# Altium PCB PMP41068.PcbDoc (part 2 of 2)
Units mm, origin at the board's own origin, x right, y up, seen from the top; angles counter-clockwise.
Board outline 71 x 50.75 mm, 4 copper layers (Top Layer, 02IS01, 03IS02, Bottom Layer), stack 0.651 mm thick; 102 components, 48 nets, 246 pads, 360 vias.
Unrouted connection lines stored in the file: 1.
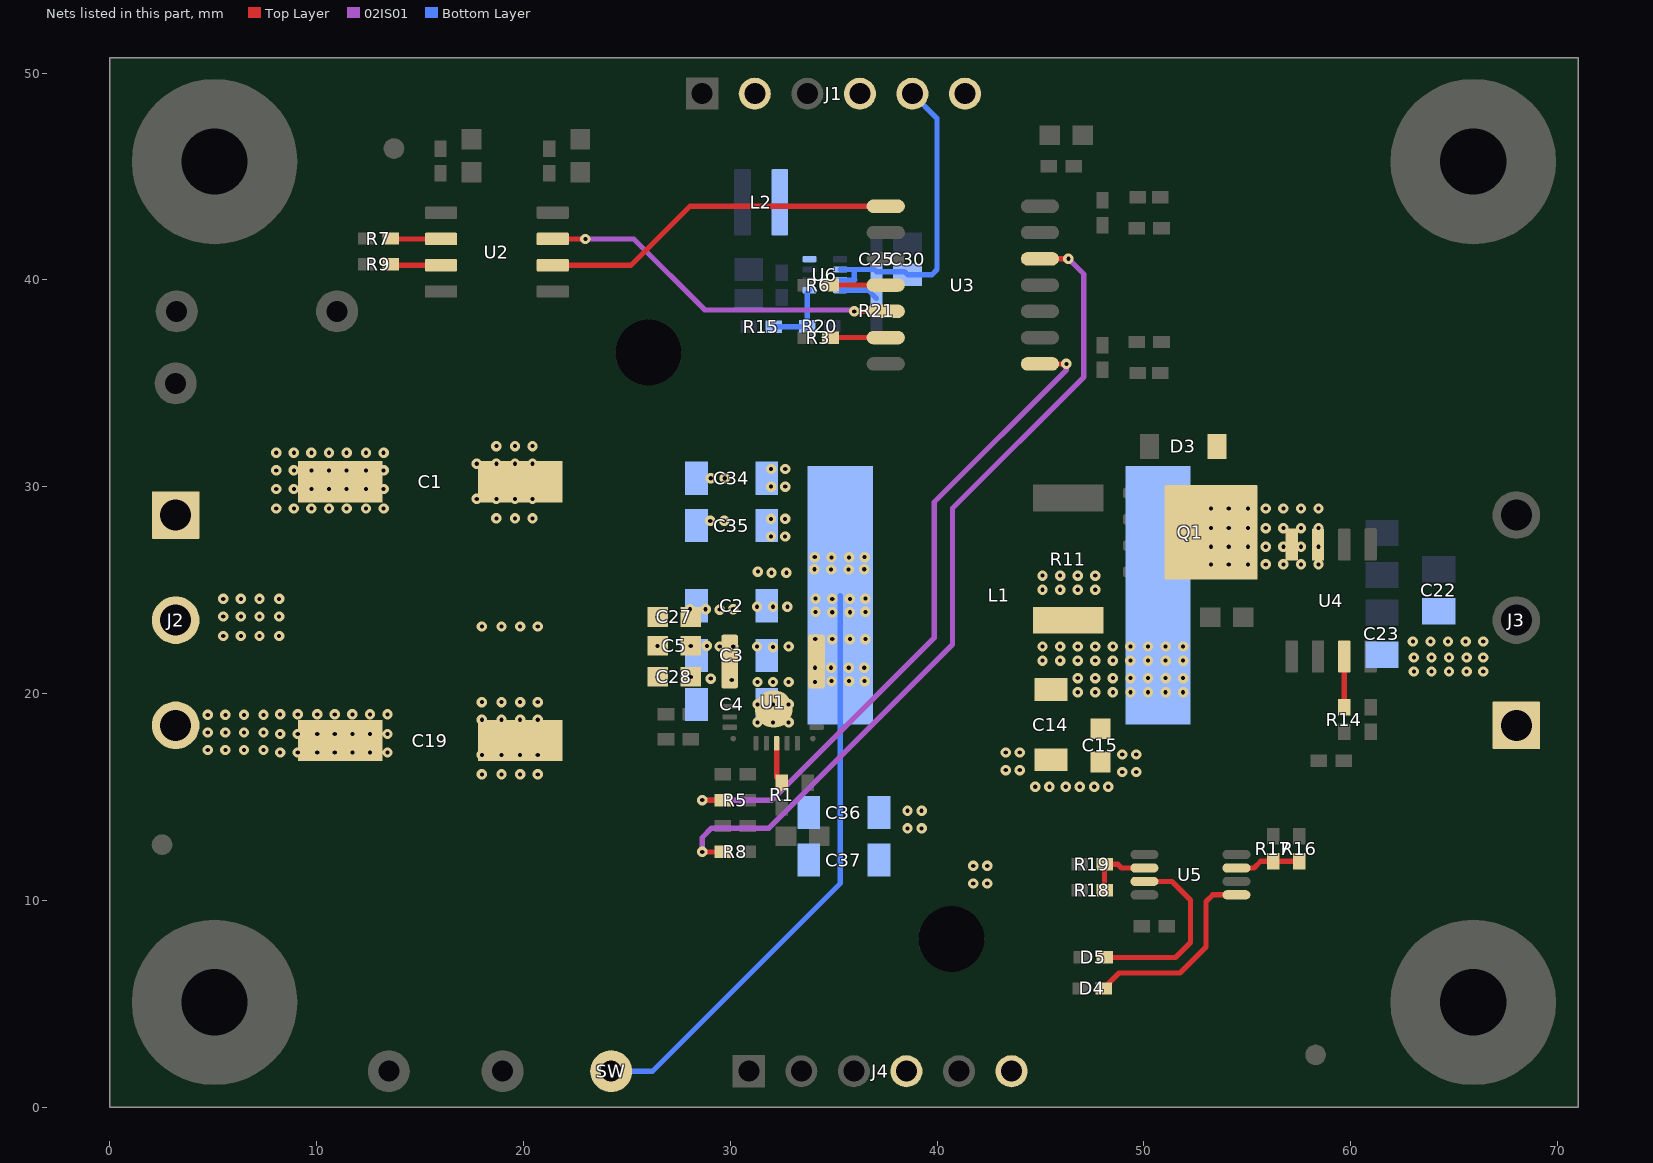
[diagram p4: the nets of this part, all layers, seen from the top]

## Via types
v1: diameter 0.5, hole 0.2, Top Layer to Bottom Layer, tented both sides, 360 vias

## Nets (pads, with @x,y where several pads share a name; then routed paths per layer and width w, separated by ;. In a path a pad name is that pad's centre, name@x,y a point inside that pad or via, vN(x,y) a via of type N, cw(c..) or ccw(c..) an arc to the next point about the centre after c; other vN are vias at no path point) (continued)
NetD3_2: D3.2 Q1.5 Q1.6 Q1.7 Q1.8 Q1.9@53.25,27.795 U4.3 U4.4
  other v1: 53.25,26.25 54.1,26.25 55.04,26.25 55.89,26.25 56.74,26.25 57.59,26.25 58.44,26.25 53.25,27.1 54.1,27.1 55.04,27.1 55.89,27.1 56.74,27.1 57.59,27.1 58.44,27.1 53.25,28 54.1,28 55.04,28 55.89,28 56.74,28 57.59,28 58.44,28 53.25,28.948 54.1,28.948 55.04,28.948 55.89,28.948 56.74,28.948 57.59,28.948 58.44,28.948
NetD4_2: D4.2 U5.1 | length 9.6
  Top Layer w0.254: D4.2@48.05,5.75 48.8,6.5 51.75,6.5 53,7.75 53,9.95 53.325,10.275 U5.1@54.475,10.275
NetD5_2: D5.2 U5.7 | length 9.1
  Top Layer w0.254: D5.2@48.1,7.25 51.525,7.25 52.25,7.975 52.25,10.025 51.35,10.925 U5.7@50.025,10.925
NetL1_1: L1.1 SW.1 U1.5 | length 28.8
  Bottom Layer w0.254: SW.1@24.25,1.75 26.25,1.75 35.325,10.825 L1.1@35.325,24.75
  other v1: 34.095,20.564 34.9,20.604 35.75,20.604 36.5,20.604 34.095,21.252 34.88,21.25 35.73,21.25 36.48,21.25 34.114,22.638 34.935,22.638 35.785,22.638 36.535,22.638 34.935,23.936 35.785,23.936 34.127,23.952 36.535,23.952 34.127,24.595 34.935,24.58 35.785,24.58 36.535,24.595 34.071,26.015 34.879,26 35.729,26 36.479,26.015 34.092,26.602 34.9,26.587 35.75,26.587 36.5,26.602
NetL2_1: L2.1 U6.4
NetR3_1: R3.1 U3.6 | length 2.7
  Top Layer w0.254: R3.1@34.85,37.21 U3.6@37.525,37.21
NetR5_1: R5.1 U3.8 | length 32.6
  Top Layer w0.254: v1(28.65,14.852) R5.1@29.65,14.852 ; U3.8@44.975,35.94 v1(46.25,35.94)
  02IS01 w0.254: v1(28.65,14.852) 32.026,14.852 39.861,22.687 39.861,29.25 46.25,35.639 v1(46.25,35.94)
NetR6_1: R6.1 U3.4 | length 2.7
  Top Layer w0.254: R6.1@34.85,39.75 U3.4@37.525,39.75
NetR7_2: R7.2 U2.2 | length 2.4
  Top Layer w0.254: R7.2@13.6,42 13.62,41.98 U2.2@16,41.98
NetR8_1: R8.1 U3.12 | length 40.6
  Top Layer w0.254: v1(28.65,12.352) R8.1@29.65,12.352 ; U3.12@44.975,41.02 v1(46.35,41.02)
  02IS01 w0.254: v1(28.65,12.352) 28.65,13.053 29.097,13.5 31.877,13.5 40.75,22.373 40.75,28.963 47.097,35.309 47.097,40.273 v1(46.35,41.02)
NetR9_2: R9.2 U2.3 | length 2.4
  Top Layer w0.254: R9.2@13.6,40.75 13.64,40.71 U2.3@16,40.71
NetR14_2: R14.2 U4.7 | length 2.4
  Top Layer w0.254: R14.2@59.685,19.35 U4.7@59.685,21.8
NetR15_1: R15.1 R20.2 U6.1 | length 3.4
  Bottom Layer w0.254: R15.1@32.1,37.73 33.705,37.73 R20.2@33.725,37.75 33.725,39.39 U6.1@33.835,39.5
NetR16_1: R16.1 R17.2 U5.3 | length 3.2
  Top Layer w0.254: U5.3@54.475,11.575 55.325,11.575 55.65,11.9 R17.2@56.25,11.9 R16.1@57.5,11.9
NetR18_1: R18.1 R19.2 U5.6 | length 3.2
  Top Layer w0.254: R18.1@48.1,10.5 R19.2@48.1,11.75 48.75,11.75 48.925,11.575 U5.6@50.025,11.575
NetR21_2: R21.2 U6.8 | length 1.9
  Bottom Layer w0.254: U6.8@35.315,39.5 36.675,39.5 R21.2@37.075,39.1
NetU2_6: U2.6 U3.1 | length 17.3
  Top Layer w0.254: U2.6@21.45,40.71 25.21,40.71 28.06,43.56 U3.1@37.525,43.56
NetU2_7: U2.7 U3.5 | length 17.5
  Top Layer w0.254: U2.7@21.45,41.98 v1(23,41.98) ; v1(36,38.48) U3.5@37.525,38.48
  02IS01 w0.254: v1(23,41.98) 25.34,41.98 28.776,38.544 35.936,38.544 v1(36,38.48)
OUT: C14.1 C15.1 L1.2 R11.1
  other v1: 46.8,20.07 47.65,20.07 48.5,20.07 49.35,20.07 50.2,20.07 51.048,20.07 51.898,20.07 46.8,20.75 47.65,20.75 48.5,20.75 49.35,20.75 50.2,20.75 51.048,20.75 51.898,20.75 45.1,21.598 45.95,21.598 46.8,21.598 47.65,21.598 48.5,21.598 49.348,21.598 50.198,21.598 51.048,21.598 51.898,21.598 45.1,22.279 45.95,22.279 46.8,22.279 47.65,22.279 48.5,22.279 49.348,22.279 50.198,22.279 51.048,22.279 51.898,22.279 45.1,25.025 45.95,25.025 46.8,25.025 47.65,25.025 45.1,25.705 45.95,25.705 46.8,25.705 47.65,25.705
U: C1.2 C14.2 C15.2 C19.1 C22.2 C23.2 C34.2 C35.2 C36.1 C37.1 J1.2 J1.4 J2.2 J3.1 J4.4 J4.6
  other v1: 41.75,10.826 42.43,10.826 41.75,11.676 42.43,11.676 38.575,13.488 39.255,13.488 38.575,14.338 39.255,14.338 44.75,15.5 45.43,15.5 46.22,15.5 46.9,15.5 47.599,15.5 48.28,15.5 18,16.1 18.948,16.1 19.848,16.1 20.698,16.1 48.95,16.212 49.63,16.212 43.32,16.302 44,16.302 18,17.04 18.948,17.04 19.848,17.04 20.698,17.04 48.95,17.062 49.63,17.062 43.32,17.152 44,17.152 18,18.74 18.948,18.74 19.848,18.74 20.698,18.74 18,19.59 18.948,19.59 19.848,19.59 20.698,19.59 63.05,21.07 63.9,21.07 64.75,21.07 65.6,21.07 66.4,21.07 63.05,21.75 63.9,21.75 64.75,21.75 65.6,21.75 66.4,21.75 63,22.525 63.85,22.525 64.7,22.525 65.55,22.525 66.4,22.525 5.5,22.79 6.35,22.79 7.25,22.79 8.198,22.79 18,23.25 18.948,23.25 19.848,23.25 20.698,23.25 5.5,23.73 6.35,23.73 7.25,23.73 8.198,23.73 5.5,24.58 6.35,24.58 7.25,24.58 8.198,24.58 31.975,27.597 32.655,27.597 31.975,28.447 32.655,28.447 18.698,28.475 19.598,28.475 20.448,28.475 17.75,29.415 18.698,29.415 19.598,29.415 20.448,29.415 31.982,30.009 32.662,30.009 31.982,30.859 32.662,30.859 17.75,31.115 18.698,31.115 19.598,31.115 20.448,31.115 18.698,31.965 19.598,31.965 20.448,31.965
VCC: R1.1 U1.14 | length 2
  Top Layer w0.254: U1.14@32.25,17.602 32.25,15.952 R1.1@32.5,15.702
VRAIL_N: C2.2 C3.2 C4.2 C5.2 C19.2 C27.2 C28.2 C36.2 C37.2 J1.6 J2.3 U1.6
  other v1: 8.25,17.152 9.1,17.152 10.04,17.152 10.89,17.152 11.74,17.152 12.59,17.152 13.44,17.152 4.75,17.275 5.6,17.275 6.5,17.275 7.448,17.275 8.25,18.052 9.1,18.052 10.04,18.052 10.89,18.052 11.74,18.052 12.59,18.052 13.44,18.052 4.75,18.125 5.6,18.125 6.5,18.125 7.448,18.125 31.325,18.614 32.075,18.614 32.825,18.614 4.75,18.975 5.6,18.975 6.5,18.975 7.448,18.975 8.25,19 9.1,19 10.04,19 10.89,19 11.74,19 12.59,19 13.44,19 31.325,19.484 32.075,19.484 32.825,19.484 31.325,20.564 32.075,20.564 32.825,20.564 26.496,20.81 32.075,22.25 31.3,22.279 32.825,22.279 26.496,22.31 26.496,23.708 31.298,24.2 32.073,24.2 32.766,24.2 32.002,25.845 32.719,25.845 31.339,25.9
VRAIL_P: C1.1 C2.1 C3.1 C4.1 C5.1 C27.1 C28.1 C34.1 C35.1 J2.1 U1.7
  other v1: 30.075,20.652 29.062,20.727 28.096,20.81 29.5,22.279 30.15,22.279 28.096,22.31 28.875,22.31 29.5,24.062 28.06,24.08 28.812,24.08 30.15,24.08 29.039,28.354 29.709,28.354 8.06,28.948 8.91,28.948 9.76,28.948 10.61,28.948 11.46,28.948 12.4,28.948 13.25,28.948 8.06,29.895 8.91,29.895 9.76,29.895 10.61,29.895 11.46,29.895 12.4,29.895 13.25,29.895 29.062,30.412 29.737,30.412 8.06,30.795 8.91,30.795 9.76,30.795 10.61,30.795 11.46,30.795 12.4,30.795 13.25,30.795 8.06,31.645 8.91,31.645 9.76,31.645 10.61,31.645 11.46,31.645 12.4,31.645 13.25,31.645
VRRGD: C25.1 C30.1 J1.5 U6.6 U6.7 | length 15.1
  Bottom Layer w0.254: U6.7@35.315,40 36.02,40 36,40.02 36,40.5 ; U6.6@35.315,40.5 36,40.5 ; J1.5@38.81,49 40,47.81 40,40.5 39.75,40.25 C30.1@38.575,40.25 38.425,40.4 C25.1@37.075,40.4 36.975,40.5 36,40.5
pads on no net: FID1.1 FID2.1 FID3.1 H1.1 H2.1 H3.1 H4.1 H5.0 H6.0 H7.0 H8.0 J3.2 LBL1.0 MP1. Q1.9@51.865,26.345 Q1.9@51.865,27.795 Q1.9@51.865,29.245 Q1.9@52.795,27.795 Q1.9@53.645,26.345 Q1.9@53.645,27.795 Q1.9@53.645,29.245 U1.1 U1.2 U1.3 U1.4 U1.8 U1.9 U1.16 U3.10 U3.11 U6.2

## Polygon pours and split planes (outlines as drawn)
U on Top Layer "U_L01_P109" (solid, remove dead copper, pour order 109): 37.525,10.758 38.033,10.25 43.725,10.25 44.25,10.775 44.25,13.752 45.498,15 49.446,15 50.025,15.579 50.025,17.35 49.875,17.5 44.313,17.5 43.5,18.313 43.5,29 43.5,33.35 43.1,33.75 31.5,33.75 30.885,33.135 30.885,27.712 31.597,27 32.986,27 33.781,27.795 36.917,27.795 37.525,27.187
VRAIL_N on Top Layer "VRAIL_N_L01_P106" (solid, remove dead copper, pour order 106): 25.25,20.25 25.25,24.08 25.877,24.707 26.75,24.707 27,24.457 27,20.25 26.75,20 25.509,20
VRAIL_P on Top Layer "VRAIL_P_L01_P084" (solid, remove dead copper, pour order 84): 15.25,25.4 16.193,24.457 24.957,24.457 25.5,25 25.518,24.982 26.975,24.982 27.5,24.457 27.5,20.378 27.878,20 28.375,20 30.287,20 30.5,20.213 30.5,33 29.75,33.75 3.389,33.75 2.25,32.611 2.25,27.57 2.665,27.155 13.495,27.155
U on Top Layer "U_L01_P078" (solid, remove dead copper, pour order 78): 18.505,28.125 17.45,29.18 17.45,31.4 18.463,32.413 20.987,32.413 21.975,31.425 21.975,29.155 20.945,28.125
U on Top Layer "U_L01_P076" (solid, remove dead copper, pour order 76): 17.75,15.75 17.5,16 17.5,19.75 17.75,20 21.75,20 22,19.75 22,16 21.75,15.75
U on Top Layer "U_L01_P074" (solid, remove dead copper, pour order 74): 15.94,23.75 21.348,23.75 23.5,21.598 23.5,15.75 23.25,15.5 15.438,15.5 15,15.937 15,19.424 13.672,20.752 2.708,20.752 2.25,21.21 2.25,25.75 2.75,26.25 13.44,26.25
OUT on Top Layer "OUT_L01_P034" (solid, remove dead copper, pour order 34): 44.5,26 47.65,26 49.25,24.4 49.25,18.095 48.905,17.75 44.602,17.75 44.25,18.102 44.25,25.75
AGND on Top Layer "AGND_L01_P020" (solid, remove dead copper, pour order 20): 34.3,16.25 34.55,16.5 36.452,16.5 36.917,16.035 36.917,10.816 36.351,10.25 26.25,10.25 25.5,11 25.5,15.75 26.5,16.75 28.5,16.75 28.75,16.5 28.75,11.75 29,11.5 34.15,11.5 35.273,12.623 35.272,13.577 34.3,14.55 34.3,15.7 34.25,15.75
AMP_VFB on Top Layer "AMP_VFB_L01_P018" (solid, remove dead copper, pour order 18): 50,26.75 50.25,27 50.25,30.488 51,31.237 51,32.5 50.5,33 45.5,33 44.25,31.75 44.25,27 44.5,26.75
AMP_OUT on Top Layer "AMP_OUT_L01_P014" (solid, remove dead copper, pour order 14): 59.752,25.5 59.25,26.002 59.25,29.645 59.855,30.25 69.25,30.25 69.5,30 69.5,25.75 69.25,25.5
NetD3_2 on Top Layer "NETD3_2_L01_P012" (solid, remove dead copper, pour order 12): 51,30.25 52,31.242 52,32.5 52.5,33 56.25,33 58.75,30.5 58.75,25.987 58.263,25.5 51,25.5 50.75,25.75 50.75,30
NetL1_1 on Top Layer "NETL1_1_L01_P010" (solid, remove dead copper, pour order 10): 33.75,20.125 33.75,26.95 34.05,27.25 36.52,27.25 36.851,26.919 36.851,20.351 36.3,19.8 34.075,19.8
VRAIL_N on Top Layer "VRAIL_N_L01_P008" (solid, remove dead copper, pour order 8): 31,26.037 31.241,26.278 31.5,26.278 33.25,26.277 33.525,26.003 33.525,18.352 33.425,18.252 31.1,18.252 31,18.352
VRAIL_N on Top Layer "VRAIL_N_L01_P004" (solid, remove dead copper, pour order 4): 2,19.5 2.75,20.25 13,20.25 14.25,19 14.25,16.75 13,15.5 2.875,15.5 2,16.375
NetL1_1 on Bottom Layer "NETL1_1_L04_P102" (solid, remove dead copper, pour order 102): 33.75,18.5 34.25,18 37.7,18 38.25,18.55 38.25,31 37.75,31.5 34.25,31.5 33.75,31
NetD3_2 on Bottom Layer "NETD3_2_L04_P100" (solid, remove dead copper, pour order 100): 53,25.75 53,29.5 53.5,30 58.25,30 58.75,29.5 58.75,25.752 58.25,25.252 58.25,25.25 53.5,25.25
U on Bottom Layer "U_L04_P098" (solid, remove dead copper, pour order 98): 31,31.197 31.5,31.697 32.759,31.697 33.25,31.206 33.25,27.143 32.803,26.697 31.38,26.697 31,27.077
U on Bottom Layer "U_L04_P094" (solid, remove dead copper, pour order 94): 37,10 36.5,10.5 36.5,17.325 36.675,17.5 51.886,17.5 51.886,17.466 52.5,16.852 52.5,10.5 52,10
VRAIL_P on Bottom Layer "VRAIL_P_L04_P092" (solid, remove dead copper, pour order 92): 16.15,24.5 21.613,24.5 24.25,21.863 24.25,14.25 26.75,11.75 29.769,11.75 30.5,12.487 30.5,18.375 30.5,33 29.75,33.75 3.389,33.75 2.25,32.611 2.25,27.57 2.665,27.155 13.495,27.155
U on Bottom Layer "U_L04_P090" (solid, remove dead copper, pour order 90): 17.905,15.75 17.75,15.905 17.75,19.925 17.863,20.038 20.657,20.038 21,19.695 21,15.867 20.882,15.75
U on Bottom Layer "U_L04_P086" (solid, remove dead copper, pour order 86): 18.505,28.125 17.45,29.18 17.45,31.4 18.463,32.413 20.987,32.413 21.975,31.425 21.975,29.155 20.945,28.125
U on Bottom Layer "U_L04_P072" (solid, remove dead copper, pour order 72): 2.25,25.75 2.75,26.25 13.44,26.25 14.25,25.44 14.25,25.418 15.918,23.75 21.345,23.75 23.5,21.595 23.5,15.75 23.25,15.5 15.455,15.5 15,15.955 15,19.424 13.672,20.752 2.708,20.752 2.25,21.21
5V on Bottom Layer "5V_L04_P070" (solid, remove dead copper, pour order 70): 31.25,11.25 31.567,11.567 31.567,12.067 32,12.5 32.425,12.5 32.75,12.175 32.75,10.5 32.25,10 1.5,10 0.5,11 0.5,40.591 1.159,41.25 29.177,41.25 29.44,40.102 3.389,40.102 1.75,38.462 1.75,12.75 3.25,11.25
VRAIL_N on Bottom Layer "VRAIL_N_L04_P054" (solid, remove dead copper, pour order 54): 2.25,19.75 2.75,20.25 13,20.25 14.25,19 14.25,16.75 13,15.5 2.875,15.5 2.25,16.125
AGND on Bottom Layer "AGND_L04_P044" (solid, remove dead copper, pour order 44): 30,38.48 30.02,38.48 30.25,38.25 32.75,38.25 33,38.5 33,39.5 32.75,39.75 30.25,39.75 30,39.5
NetL2_1 on Bottom Layer "NETL2_1_L04_P042" (solid, remove dead copper, pour order 42): 33.007,45.5 33.25,45.257 33.25,42.75 34.25,41.75 34.25,41 34.091,40.841 33.409,40.841 32.5,41.75 32.325,41.75 31.75,42.325 31.75,45.25 32,45.5
no net on Bottom Layer "NONET_L04_P040" (solid, remove dead copper, pour order 40): 31.775,42.25
5V on Bottom Layer "5V_L04_P038" (solid, remove dead copper, pour order 38): 31.554,40 31.75,40.203 31.75,41.25 31.5,41.5 31.5,45.25 31.25,45.5 29.5,45.5 29.062,45.062 29.062,37.73 29.292,37.5 29.52,37.5 29.75,37.73 29.75,39.696 30.054,40
U on Bottom Layer "U_L04_P032" (solid, remove dead copper, pour order 32): 62.2,19.05 62.2,16.65 63.1,15.75 68.5,15.75 69.273,16.523 69.273,23.727 68.25,24.75 63.25,24.75 63,24.5 63,23 62.75,22.75 60.25,22.75 60.014,22.514 60,22.514 60,21.25
NetC23_1 on Bottom Layer "NETC23_1_L04_P030" (solid, remove dead copper, pour order 30): 60,23.25 60,26.25 60.25,26.5 62.5,26.5 62.75,26.25 62.75,23.25 62.5,23 60.25,23
AMP_OUT on Bottom Layer "AMP_OUT_L04_P028" (solid, remove dead copper, pour order 28): 59.75,29.75 60.25,30.25 69.25,30.25 69.5,30 69.5,25.705 69.045,25.25 63.25,25.25 63,25.5 63,26.25 62.5,26.75 60.25,26.75 59.75,27.25
OUT on Bottom Layer "OUT_L04_P026" (solid, remove dead copper, pour order 26): 44.25,17.75 43.25,18.75 43.25,30 44.5,31.25 52.25,31.25 52.5,31 52.5,18.364 51.886,17.75
VRAIL_N on Bottom Layer "VRAIL_N_L04_P022" (solid, remove dead copper, pour order 22): 33.25,18.187 34.5,16.937 34.5,10.75 33.75,10 33.25,10 31,10 31,25.869 31.408,26.278 32.988,26.277 33.25,26.016
U on 02IS01 "U_L02_P104" (solid, remove dead copper, pour order 104): 1.25,20.752 0.75,21.252 0.75,25.237 1.265,25.752 10.907,25.752 12,24.659 12,24 8.75,20.75
AGND on 02IS01 "AGND_L02_P066" (solid, remove dead copper, pour order 66): 32,5.777 32,4.138 31.112,3.25 29.773,3.25 29.51,2.987 29.51,0.997 29.013,0.5 13.389,0.5 13.389,2.019 27.672,16.302 34.076,16.302 40.347,22.574 40.347,29.322 45.275,34.25 18.751,34.25 18.259,34.741 18.259,44.509 21,47.25 23.25,47.25 25,45.5 36.75,45.5 38.5,47.25 38.5,49.875 39,50.375 39.125,50.25 70,50.25 70.5,49.75 70.5,25.25 70,24.75 55.52,24.75 54.1,23.33 54.1,19.82 49.53,15.25 41.473,15.25
GND2 on 02IS01 "GND2_L02_P064" (solid, remove dead copper, pour order 64): 34.5,0.5 34.5,5.171 42.817,13.488 50.636,13.488 56.75,19.602 56.75,23.499 57.5,24.2 70.05,24.2 70.5,23.75 70.5,1 70,0.5
no net on 02IS01 "NONET_L02_P062" (solid, remove dead copper, pour order 62): 28.75,5.636
GND1 on 02IS01 "GND1_L02_P058" (solid, remove dead copper, pour order 58): 0.81,34.25 0.5,34.56 0.5,49.5 1.25,50.25 37.75,50.25 37.75,47.25 36.5,46 25.12,46 23.37,47.75 21,47.75 17.75,44.5 17.75,34.76 17.24,34.25
VRAIL_P on 02IS01 "VRAIL_P_L02_P048" (solid, remove dead copper, pour order 48): 0.5,27.462 0.5,31.609 2.641,33.75 13.25,33.75 14.25,32.75 14.25,27.447 13.053,26.25 1.712,26.25
VRAIL_N on 02IS01 "VRAIL_N_L02_P046" (solid, remove dead copper, pour order 46): 13.75,0.5 13.75,3.052 27.55,16.852 34.429,16.852 40.347,22.77 40.347,29.347 44.75,33.75 15.75,33.75 14.75,32.75 14.75,25.981 9.019,20.25 2.75,20.25 1.13,20.25 0.5,19.62 0.5,1.5 1.5,0.5
U on 03IS02 "U_L03_P060" (solid, remove dead copper, pour order 60): 0.506,34.744 0.5,34.737 0.5,1.25 1.25,0.5 70,0.5 70.5,1 70.5,49.75 70,50.25 1,50.25 0.5,49.75 0.5,35
VRAIL_P on 03IS02 "VRAIL_P_L03_P052" (solid, remove dead copper, pour order 52): 0.506,27.5 1.256,26.75 13.295,26.75 14.25,27.705 14.25,32.75 13.25,33.75 1.305,33.75 0.506,32.951
VRAIL_N on 03IS02 "VRAIL_N_L03_P050" (solid, remove dead copper, pour order 50): 0.506,19.826 0.93,20.25 13,20.25 14.25,19 14.25,16.75 13,15.5 1,15.5 0.506,15.994

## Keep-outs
Keep-Out Layer:
  text ".Layer_Name" at 14.541,-25.527 h1.52

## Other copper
Top Layer:
  rectangle net U: 38.275,13.021 41.775,15.618
  rectangle net U: 38.275,28.653 41.775,31.25
  rectangle net VRAIL_P: 25,28.653 28.5,31.25
  text ".Layer_Name" at 12.542,-25.527 h1.52
02IS01:
  rectangle net VRAIL_N: 31.628,16.545 32.596,17.259
  rectangle net AGND: 31.627,16.101 32.596,16.64
  rectangle net AGND: 40.16,47.5 42.66,50.25
  rectangle net GND2: 42.41,0.25 44.91,3
  rectangle net GND2: 37.33,0.25 39.83,3
  rectangle net GND1: 35.08,47.5 37.58,50.25
  rectangle net GND1: 30,47.5 32.5,50.25
Bottom Layer:
  text ".Layer_Name" at 14.541,-25.527 h1.52

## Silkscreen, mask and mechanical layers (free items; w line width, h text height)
Top Overlay:
  lines w0.254: 50.75,22.79 52.936,20.604 52.996,20.604 53,20.604
  text "PMP41068" at 28.25,45.55 h2.5
  text "Audio-Out" at 65.25,31.965 h1.2
  text "VIN+" at 2.5,31.75 h1.2
  text "GND" at 8.75,23.55 h1.2
  text "GND" at 66.45,14.25 h1.2
  text "VIN-" at 3.75,14 h1.2
  text ".Layer_Name" at 14.541,-25.527 h1.52
Bottom Overlay:
  text "NULL" at 4.628,37.886 h1.2
  text "GND" at 12.5,37.25 h1.2
  text "Audio-In" at 4.478,34.481 h1.2
  text "AMP_OUT" at 64.5,30.625 h1.2
  text "VRAIL_P" at 2,26.25 h1.2
  text "U" at 2.25,21.21 h1.2
  text "NULL" at 66.836,20.981 h1.2
  text "U" at 67.3,15.75 h1.2
  text "VRAIL_N" at 2.378,15.636 h1.2
  text ".Layer_Name" at 14.541,-25.527 h1.52
Top Paste:
  text ".Layer_Name" at 14.541,-25.527 h1.52
Bottom Paste:
  text ".Layer_Name" at 14.541,-25.527 h1.52
Top Solder:
  text ".Layer_Name" at 14.541,-25.527 h1.52
  text ".Layer_Name" at 14.541,-25.527 h1.52
Bottom Solder:
  text ".Layer_Name" at 14.541,-25.527 h1.52
Drill Guide:
  text ".Layer_Name" at 14.541,-25.527 h1.52
M1 Board Outline:
  lines w0.254: 0,0 0,50.75 71,50.75 71,0 50.8,0 0,0
  text ".Layer_Name" at 12.542,-25.527 h1.52
M2 Board Dimensions:
  rectangle: 3.061,-13.881 12.586,-10.706
  rectangle: -0.114,-10.706 3.061,-7.531
  lines w0.178: -0.114,-10.706 25.286,-10.706 ; 3.061,-13.881 3.061,-7.531 ; 6.236,-13.881 6.236,-7.531 ; 12.586,-13.881 12.586,-7.531 ; 18.936,-13.881 18.936,-7.531 ; -0.114,-13.881 -0.114,-7.531 25.286,-7.531 25.286,-13.881 -0.114,-13.881
  text ".Layer_Name" at 12.542,-25.527 h1.52
M3 3D STEP Top:
  text ".Layer_Name" at 12.542,-25.527 h1.52
M4 3D STEP Bottom:
  text ".Layer_Name" at 12.542,-25.527 h1.52
M5 Assembly Top:
  lines w0.254: -8.031,-27.347 140.56,-27.347 ; -8.031,-22.183 140.56,-22.183 ; -8.031,-17.018 -8.031,-32.512 93.696,-32.512 ; 31.999,-32.512 -8.018,-32.512 -8.018,-17.018 140.56,-17.018 140.56,-32.512 81.596,-32.512 ; 49.98,-32.512 49.98,-17.018 ; 76.162,-22.183 76.162,-17.018 ; 94.498,-22.183 94.498,-17.018 ; 107.297,-32.677 107.297,-27.525
  text "COMPONENTS MARKED 'DNP' SHOULD NOT BE POPULATED." at 26.085,-11.811 h1.52
  text "ASSEMBLY VARIANT:" at 26.072,-14.745 h1.52
  text ".VariantName" at 52.186,-14.745 h1.52
  text "PCB VIEWED FROM TOP SIDE" at -6.918,-20.375 h1.52
  text "BOARD #:" at 51.085,-20.375 h1.52
  text ".PRJ_Number" at 62.741,-20.375 h1.52
  text "REV:" at 80.191,-20.375 h1.52
  text ".PCB_Rev" at 86.095,-20.375 h1.52
  text "SVN REV:" at 96.276,-20.375 h1.52
  text ".VersionControl_RevNumber" at 108.829,-20.375 h1.52
  text "TID #:" at 51.085,-25.54 h1.52
  text ".TID" at 62.741,-25.54 h1.52
  text "PLOT NAME =" at -6.918,-30.755 h1.52
  text ".plot_File_Name" at 12.542,-30.755 h1.52
  text "GENERATED    :" at 51.136,-30.755 h1.52
  text ".Print_Date" at 69.521,-30.755 h1.52
  text ".Print_Time" at 84.538,-30.755 h1.52
  text "TEXAS INSTRUMENTS" at 111.656,-30.755 h1.52
M6 Assembly Bottom:
  lines w0.254: -8.044,-22.195 140.56,-22.195 ; -7.993,-27.36 140.56,-27.36 ; 25.619,-32.69 25.619,-27.538 ; 39.418,-22.195 39.418,-17.031 ; 51.82,-32.525 140.56,-32.525 103.517,-32.525 ; 57.92,-32.525 -8.044,-32.525 -8.044,-17.031 140.56,-17.031 ; 58.254,-22.195 58.254,-17.031 ; 84.436,-32.525 84.436,-17.031 ; 140.534,-32.525 140.534,-17.031 ; 140.547,-32.525 140.547,-17.031
  text "COMPONENTS MARKED 'DNP' SHOULD NOT BE POPULATED." at 144.777,-11.798 h1.52
  text ".VariantName" at 110.759,-14.745 h1.52
  text "ASSEMBLY VARIANT:" at 136.15,-14.745 h1.52
  text ".VersionControl_RevNumber" at 26.187,-20.388 h1.52
  text "SVN REV:" at 38.54,-20.388 h1.52
  text ".PCB_Rev" at 48.821,-20.388 h1.52
  text "REV:" at 54.925,-20.388 h1.52
  text ".PRJ_Number" at 70.175,-20.388 h1.52
  text "BOARD #:" at 82.031,-20.388 h1.52
  text "PCB VIEWED FROM BOTTOM SIDE" at 139.434,-20.388 h1.52
  text ".TID" at 70.675,-25.552 h1.52
  text "TID #:" at 82.031,-25.552 h1.52
  text "TEXAS INSTRUMENTS" at 21.36,-30.768 h1.52
  text ".Print_Time" at 51.378,-30.768 h1.52
  text ".Print_Date" at 67.095,-30.768 h1.52
  text "GENERATED    :" at 86.98,-30.768 h1.52
  text ".plot_File_Name" at 122.474,-30.768 h1.52
  text "PLOT NAME =" at 139.434,-30.768 h1.52
M9 Title Sheet:
  drawing of 55 lines, arcs and shapes, not listed
  text "1" at 16.671,131.699 h1.78
  text "2" at 76.564,131.699 h1.78
  text "3" at 136.931,131.699 h1.78
  text "4" at 197.265,131.699 h1.78
  text "A" at -11.201,109.093 h1.78
  text "A" at 224.892,109.093 h1.78
  text "B" at -11.201,61.443 h1.78
  text "B" at 224.892,61.443 h1.78
  text "C" at -11.201,13.792 h1.78
  text "C" at 224.892,13.792 h1.78
  text "PROJECT TITLE:" at 147.803,-14.453 h1.14
  text ".PRJ_Title" at 149.073,-17.839 h1.78
  text "DESIGNED FOR:" at 147.803,-22.098 h1.14
  text ".PRJ_Customer" at 149.073,-25.654 h1.78
  text "FILE NAME:" at 147.803,-29.718 h1.14
  text ".PCB_File_Name_No_Path" at 149.073,-32.766 h1.78
  text "D" at -11.201,-33.757 h1.78
  text "D" at 224.892,-33.757 h1.78
  text "Texas Instruments (TI) and/or its licensors do not warrant the accuracy or completeness of this specification" at 24.371,-36.877 h1.14
  text "ENGINEER:" at 147.803,-37.084 h1.14
  text "LAYOUT BY:" at 186.03,-37.084 h1.14
  text "or any information contained therein. TI and/or its licensors do not warrant that this design will meet" at 23.229,-39.738 h1.14
  text ".PRJ_Engineer" at 149.073,-41.021 h1.78
  text ".PCB_Layout" at 187.312,-41.021 h1.78
  text "the specifications, will be suitable for your application or fit for any particular purpose, or will operate in" at 23.229,-42.6 h1.14
  text "ALTIUM DESIGNER VERSION:" at 186.03,-44.958 h1.14
  text "an implementation. TI and/or its licensors do not warrant that the design is production worthy. You should" at 23.229,-45.462 h1.14
  text "completely validate and test your design implementation to confirm the system functionality for your application." at 24.371,-48.323 h0.7
  text ".print_Scale" at 149.073,-48.345 h1.78
  text ".Application_BuildNumber" at 187.312,-48.345 h1.78
  text "1" at 16.671,-53.721 h1.78
  text "2" at 76.564,-53.721 h1.78
  text "3" at 136.931,-53.721 h1.78
  text "4" at 197.265,-53.721 h1.78
M10 Fab Notes:
  drawing of 189 lines, arcs and shapes, not listed
  text "DESIGN INFORMATION" at 174.117,127.385 h1.52
  text "MIN. TRACK WIDTH:" at 157.746,124.029 h1.52
  text "10" at 185.59,124.03 h1.52
  text "MIL" at 189.521,124.029 h1.52
  text "7.874" at 181.25,121 h1.52
  text "MIN. CLEARANCE:" at 157.746,120.877 h1.52
  text "MIL" at 189.521,120.877 h1.52
  text "MIN. VIA PAD SIZE:" at 157.746,117.724 h1.52
  text "24" at 184.828,117.724 h1.52
  text "MIL" at 189.521,117.724 h1.52
  text "0.05mm (2MIL)" at 175.399,114.424 h1.52
  text "MINIMUM ANNULAR RING" at 149.383,114.216 h1.52
  text "EXTERNAL" at 193.382,114.216 h1.52
  text "PER" at 154.463,111.418 h1.52
  text "IPC-D-275 CLASS 2 LEVEL C" at 160.051,111.418 h1.52
  text "MIL, HOLES" at 197.852,108.866 h1.52
  text "+/-" at 187.884,108.648 h1.52
  text "+/-" at 209.575,108.648 h1.52
  text "REGISTRATION TOLERANCES:" at 149.383,108.621 h1.52
  text "METAL" at 179.857,108.621 h1.52
  text "5" at 194.493,108.621 h1.52
  text "3" at 215.651,108.621 h1.52
  text "MIL" at 218.604,108.621 h1.52
  text "HOLE SIZE TOLERANCE (UNLESS OTHERWISE SPECIFIED):" at 149.383,106.124 h1.52
  text "+/-" at 209.575,106.051 h1.52
  text "3" at 215.651,106.024 h1.52
  text "MIL" at 218.604,106.024 h1.52
  text "MATERIAL:" at 147.484,102.528 h1.52
  text "FR-4 High Tg" at 172.54,99.263 h1.52
  text "X" at 168.871,99.06 h1.52
  text "FR-4" at 158.178,98.945 h1.52
  text "OTHER" at 195.973,98.945 h1.52
  text "62 MIL (1.6mm) +/-10%" at 166.308,95.312 h1.52
  text "X" at 163.258,95.25 h1.52
  text "THICKNESS:" at 149.383,95.104 h1.52
  text "OTHER" at 198.944,95.104 h1.52
  text "TOLERANCE:" at 149.383,91.59 h1.52
  text "X" at 170.928,91.59 h1.52
  text "ANSI IPC-6012 TYPE 3 CLASS 2" at 175.45,91.59 h1.52
  text "OTHER +/-" at 175.449,87.928 h1.52
  text "BOW & TWIST:" at 149.383,84.24 h1.52
  text "X" at 170.928,84.24 h1.52
  text "ANSI IPC-6012 TYPE 3 CLASS 2" at 175.45,84.24 h1.52
  text "OTHER +/-" at 175.449,80.514 h1.52
  text "DRILLING:" at 147.484,77.196 h1.52
  text "NC_DRILL FILES" at 192.213,74.525 h1.52
  text "REFERENCE:" at 149.383,74.425 h1.52
  text "X" at 166.077,74.422 h1.52
  text "AS SHOWN" at 170.598,74.425 h1.52
  text "X" at 188.962,74.425 h1.52
  text "OTHER" at 199.783,70.811 h1.52
  text "PTH COPPER THICKNESS:" at 149.375,70.722 h1.52
  text "X" at 178.312,70.722 h1.52
  text "20-30 um" at 181.563,70.722 h1.52
  text "BOARD FINISH:" at 147.484,66.973 h1.52
  text "SILKSCREEN:" at 151.427,64.176 h1.52
  text "X" at 175.754,64.176 h1.52
  text "TOP" at 178.726,64.176 h1.52
  text "X" at 188.708,64.176 h1.52
  text "BOTTOM" at 191.705,64.176 h1.52
  text "SILKSCREEN COLOR:" at 151.427,60.234 h1.52
  text "X" at 175.729,60.234 h1.52
  text "WHITE" at 178.726,60.234 h1.52
  text "OTHER" at 191.705,60.234 h1.52
  text "X" at 179.056,56.59 h1.52
  text "GREEN" at 182.053,56.59 h1.52
  text "OTHER" at 197.751,56.59 h1.52
  text "SOLDER RESIST COLOR:" at 151.427,56.416 h1.52
  text "X" at 179.056,52.672 h1.52
  text "MATTE" at 182.053,52.672 h1.52
  text "SEMI-GLOSS" at 197.739,52.656 h1.52
  text "IMMERSION GOLD (ENIG)" at 174.433,48.284 h1.52
  text "ENEPIG" at 208.407,48.1 h1.52
  text "SURFACE FINISH:" at 147.484,48.075 h1.52
  text "X" at 169.912,48.075 h1.52
  text "IMM. TIN/SILVER OR EQUIV" at 155.854,44.587 h1.52
  text "OTHER" at 192.213,44.487 h1.52
  text "ARRAY/PANEL:" at 147.484,40.541 h1.52
  text "CUT AND TRIM PER M1 BOARD OUTLINE" at 174.433,40.332 h1.52
  text "N.C. ROUTE" at 174.433,36.878 h1.52
  text "X" at 191.909,36.878 h1.52
  text "V. SCORE" at 196.43,36.878 h1.52
  text "CERTIFICATION:" at 147.484,33.598 h1.52
  text "MATERIALS AND WORKMANSHIP FOR ALL PCBS" at 165.899,33.598 h1.52
  text "TO MEET OR EXCEED THE REQUIREMENTS OF:" at 165.899,31.209 h1.52
  text "X" at 156.692,27.942 h1.52
  text "ANSI IPC-A-600F CLASS ->" at 159.943,27.942 h1.52
  text "X" at 201.802,27.942 h1.52
  text "2" at 204.596,27.942 h1.52
  text "1" at 196.595,27.904 h1.52
  text "3" at 213.588,27.904 h1.52
  text "X" at 177.317,24.191 h1.52
  text "RoHS" at 180.568,24.191 h1.52
  text "OTHER" at 196.935,24.191 h1.52
  text "PER ORDER" at 207.021,24.191 h1.52
  text "ALL BOARDS MUST MEET OR EXCEED UL94-V0 REQUIREMENTS." at 148.184,20.284 h1.52
  text "PCB MUST BEAR THE UL94V-0 UL REGISTERED MATERIAL ID NUMBER" at 148.184,17.336 h1.52
  text "ADDITIONAL REQUIREMENTS:" at 147.484,13.032 h1.52
  text "MICROSECTION:" at 149.383,10.311 h1.52
  text "YES" at 172.389,10.311 h1.52
  text "REQUIRED" at 194.271,6.645 h1.52
  text "BARE BOARD ELEC. TEST:" at 149.383,6.573 h1.52
  text "NONE" at 182.549,6.573 h1.52
  text "X" at 191.274,6.573 h1.52
  text "PER ORDER" at 209.308,6.573 h1.52
  text "XX MIL VIAS REQUIRE NON-CONDUCTIVE FILL AND PLANARIZE" at 153.654,1.367 h1.5
  text "XX MIL VIAS REQUIRE CONDUCTIVE FILL AND PLANARIZE" at 153.857,-1.274 h1.52
  text "OUTER XX MIL TRACES REQUIRE 50 OHM SINGLE-ENDED IMPEDANCE" at 153.832,-5.424 h1.47
  text "LAYER 2 & 3 (INNER LAYERS) XX MIL WIDE, XX MIL SPACE / TRACES REQUIRE 100 OHM DIFFERENTIAL IMPEDANCE" at 153.629,-11.411 h1.52
  text ".Layer_Name" at 12.542,-25.527 h1.52
M11 Gerber Information:
  lines w0.254: -8.031,-27.347 140.56,-27.347 ; -8.031,-22.183 140.56,-22.183 ; -8.031,-17.018 -8.031,-32.512 93.696,-32.512 ; 31.999,-32.512 -8.018,-32.512 -8.018,-17.018 140.56,-17.018 140.56,-32.512 81.596,-32.512 ; 49.98,-32.512 49.98,-17.018 ; 76.162,-22.183 76.162,-17.018 ; 94.498,-22.183 94.498,-17.018 ; 107.297,-32.677 107.297,-27.525
  text "ALL ARTWORK VIEWED FROM TOP SIDE" at -6.918,-20.375 h1.52
  text "BOARD #:" at 51.085,-20.375 h1.52
  text ".PRJ_Number" at 62.741,-20.375 h1.52
  text "REV:" at 80.191,-20.375 h1.52
  text ".PCB_Rev" at 86.095,-20.375 h1.52
  text "SVN REV:" at 96.276,-20.375 h1.52
  text ".VersionControl_RevNumber" at 108.829,-20.375 h1.52
  text "LAYER NAME =" at -6.918,-25.527 h1.52
  text "TID #:" at 51.085,-25.54 h1.52
  text ".TID" at 62.741,-25.54 h1.52
  text "PLOT NAME =" at -6.918,-30.755 h1.52
  text ".plot_File_Name" at 12.542,-30.755 h1.52
  text "GENERATED    :" at 51.136,-30.755 h1.52
  text ".Print_Date" at 69.521,-30.755 h1.52
  text ".Print_Time" at 84.538,-30.755 h1.52
  text "TEXAS INSTRUMENTS" at 111.656,-30.755 h1.52
M12 Stackup:
  drawing of 295 lines, arcs and shapes, not listed
  text "Layer" at 27.521,111.582 h1.52
  text "Name" at 37.933,111.582 h1.52
  text "Material" at 61.548,111.582 h1.52
  text "Thickness" at 83.386,111.582 h1.52
  text "Constant" at 99.892,111.582 h1.52
  text "Board Layer Stack" at 114.367,111.582 h1.52
  text "1" at 27.521,108.534 h1.52
  text "Top Overlay" at 37.933,108.534 h1.52
  text "2" at 27.521,105.486 h1.52
  text "Top Solder" at 37.933,105.486 h1.52
  text "Solder Resist" at 61.548,105.486 h1.52
  text "0.40mil" at 83.386,105.486 h1.52
  text "3.5" at 99.892,105.486 h1.52
  text "3" at 27.521,102.438 h1.52
  text "Top Layer" at 37.933,102.438 h1.52
  text "Copper" at 61.548,102.438 h1.52
  text "1.40mil" at 83.386,102.438 h1.52
  text "4" at 27.521,99.39 h1.52
  text "Dielectric1" at 37.933,99.39 h1.52
  text "FR-4 High Tg" at 61.548,99.39 h1.52
  text "5.00mil" at 83.386,99.39 h1.52
  text "4.2" at 99.892,99.39 h1.52
  text "5" at 27.521,96.342 h1.52
  text "02IS01" at 37.933,96.342 h1.52
  text "Copper" at 61.548,96.342 h1.52
  text "1.42mil" at 83.386,96.342 h1.52
  text "6" at 27.521,93.294 h1.52
  text "Dielectric 2" at 37.933,93.294 h1.52
  text "10.00mil" at 83.386,93.294 h1.52
  text "4.2" at 99.892,93.294 h1.52
  text "7" at 27.521,90.246 h1.52
  text "03IS02" at 37.933,90.246 h1.52
  text "Copper" at 61.548,90.246 h1.52
  text "1.42mil" at 83.386,90.246 h1.52
  text "8" at 27.521,87.198 h1.52
  text "Dielectric 3" at 37.933,87.198 h1.52
  text "5.00mil" at 83.386,87.198 h1.52
  text "4.2" at 99.892,87.198 h1.52
  text "9" at 27.521,84.15 h1.52
  text "Bottom Layer" at 37.933,84.15 h1.52
  text "Copper" at 61.548,84.15 h1.52
  text "1.40mil" at 83.386,84.15 h1.52
  text "10" at 27.521,81.102 h1.52
  text "Bottom Solder" at 37.933,81.102 h1.52
  text "Solder Resist" at 61.548,81.102 h1.52
  text "0.40mil" at 83.386,81.102 h1.52
  text "3.5" at 99.892,81.102 h1.52
  text "11" at 27.521,78.054 h1.52
  text "Bottom Overlay" at 37.933,78.054 h1.52
  text ".Layer_Name" at 12.542,-25.527 h1.52
M13 Component Bodies Top:
  text ".Layer_Name" at 12.542,-25.527 h1.52
M14 Component Bodies Bottom:
  text ".Layer_Name" at 12.542,-25.527 h1.52
M15 Courtyards Top:
  text ".Layer_Name" at 12.542,-25.527 h1.52
M16 Courtyards Bottom:
  text ".Layer_Name" at 12.542,-25.527 h1.52
Drill Drawing:
  circle w0.254: c64.306,90.88 r0.702
  lines w0.254: 63.604,80.705 65.007,80.705 65.007,82.109 63.604,82.109 63.604,80.705 ; 63.604,84.214 63.955,84.214 63.955,83.863 64.656,83.863 64.656,84.214 65.007,84.214 65.007,84.916 64.656,84.916 64.656,85.267 63.955,85.267 63.955,84.916 63.604,84.916 63.604,84.214 ; 63.604,88.424 65.007,88.424 64.306,87.021 63.604,88.424 ; 63.604,93.687 63.955,93.687 64.306,93.336 64.656,93.687 65.007,93.687 64.656,94.038 65.007,94.389 64.656,94.389 64.306,94.74 63.955,94.389 63.604,94.389 63.955,94.038 63.604,93.687
  lines w0.305: 62.332,79.758 144.411,79.758 ; 62.332,95.547 144.411,95.547 ; 70.913,76.6 70.913,98.704 ; 79.346,76.6 79.346,98.704 ; 95.515,76.6 95.515,98.704 ; 102.097,76.6 102.097,98.704 ; 111.626,76.6 111.626,98.704 ; 130.024,76.6 130.024,98.704 ; 62.332,76.6 144.411,76.6 144.411,98.704 62.332,98.704 62.332,76.6
  text "Symbol" at 64.226,96.494 h1.83
  text "Quantity" at 71.861,96.494 h1.83
  text "Finished Hole Size" at 80.293,96.494 h1.83
  text "Plated" at 96.462,96.494 h1.83
  text "Hole Type" at 103.044,96.494 h1.83
  text "Drill Layer Pair" at 112.573,96.494 h1.83
  text "Hole Tolerance" at 130.971,96.494 h1.83
  text "2" at 71.861,93.336 h1.52
  text "125.20mil (3.180mm)" at 80.293,93.336 h1.52
  text "NPTH" at 96.462,93.336 h1.52
  text "Round" at 103.044,93.336 h1.52
  text "Top Layer - Bottom Layer" at 112.573,93.336 h1.52
  text "360" at 71.861,90.179 h1.52
  text "7.87mil (0.200mm)" at 80.293,90.179 h1.52
  text "PTH" at 96.462,90.179 h1.52
  text "Round" at 103.044,90.179 h1.52
  text "Top Layer - Bottom Layer" at 112.573,90.179 h1.52
  text "18" at 71.861,87.021 h1.52
  text "40.00mil (1.016mm)" at 80.293,87.021 h1.52
  text "PTH" at 96.462,87.021 h1.52
  text "Round" at 103.044,87.021 h1.52
  text "Top Layer - Bottom Layer" at 112.573,87.021 h1.52
  text "6" at 71.861,83.863 h1.52
  text "59.06mil (1.500mm)" at 80.293,83.863 h1.52
  text "PTH" at 96.462,83.863 h1.52
  text "Round" at 103.044,83.863 h1.52
  text "Top Layer - Bottom Layer" at 112.573,83.863 h1.52
  text "4" at 71.861,80.705 h1.52
  text "125.98mil (3.200mm)" at 80.293,80.705 h1.52
  text "PTH" at 96.462,80.705 h1.52
  text "Round" at 103.044,80.705 h1.52
  text "Top Layer - Bottom Layer" at 112.573,80.705 h1.52
  text "390 Total" at 71.861,77.548 h1.52
  text ".Layer_Name" at 12.542,-25.527 h1.52
M17 Embedded Cavity:
  text ".Layer_Name" at 12.542,-25.527 h1.52
M18 Embedded Assembly:
  text ".Layer_Name" at 12.542,-25.527 h1.52
M19 Embedded Keepout:
  text ".Layer_Name" at 12.642,-25.627 h1.52

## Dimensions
-0.114,-13.881 to 25.286,-13.881 on M2 Board Dimensions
